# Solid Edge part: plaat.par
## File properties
Author: Kadik
Template: Iso Part.par
Last saved by: Kadik
Revision: 2
Application: Solid Edge
Accuracy: 0,990
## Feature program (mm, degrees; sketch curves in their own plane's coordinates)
sketch for "unnamed Protrusion 1" plane through (10.8674, 0, 10.8674) normal (0, -1, 0) x-axis (1, 0, 0)
  circle centre (-10.8674, -10.8674) radius 113
extrude "unnamed Protrusion 1" add finite 15 along -normal
sketch for "ExtrudedProtrusion_2" plane through (0, 15, 0) normal (0, 1, 0) x-axis (-1, 0, 0)
  circle centre (-60.3882, 20.7488) radius 8.0518
extrude "ExtrudedProtrusion_2" add finite 70 along +normal
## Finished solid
Body 1: solid body, 5 faces, 4 edges, 0 vertices.
  Faces by surface: plane 3, cylinder 2
  Edges by curve: circle 4
Bounding box of the edges (mm): 226.000 x 85.000 x 226.000, from (-113, 0, -113) to (113, 85, 113).
Cylindrical faces by radius (mm): R8.0518 x1, R113 x1
Planar faces by outward normal: +y 2, -y 1
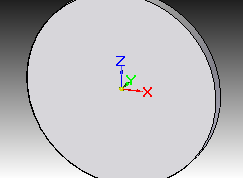
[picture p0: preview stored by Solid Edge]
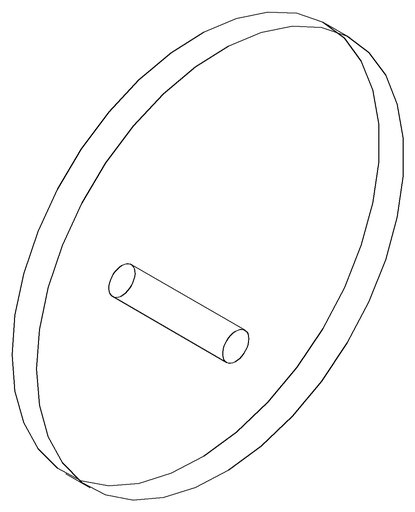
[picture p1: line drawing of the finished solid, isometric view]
